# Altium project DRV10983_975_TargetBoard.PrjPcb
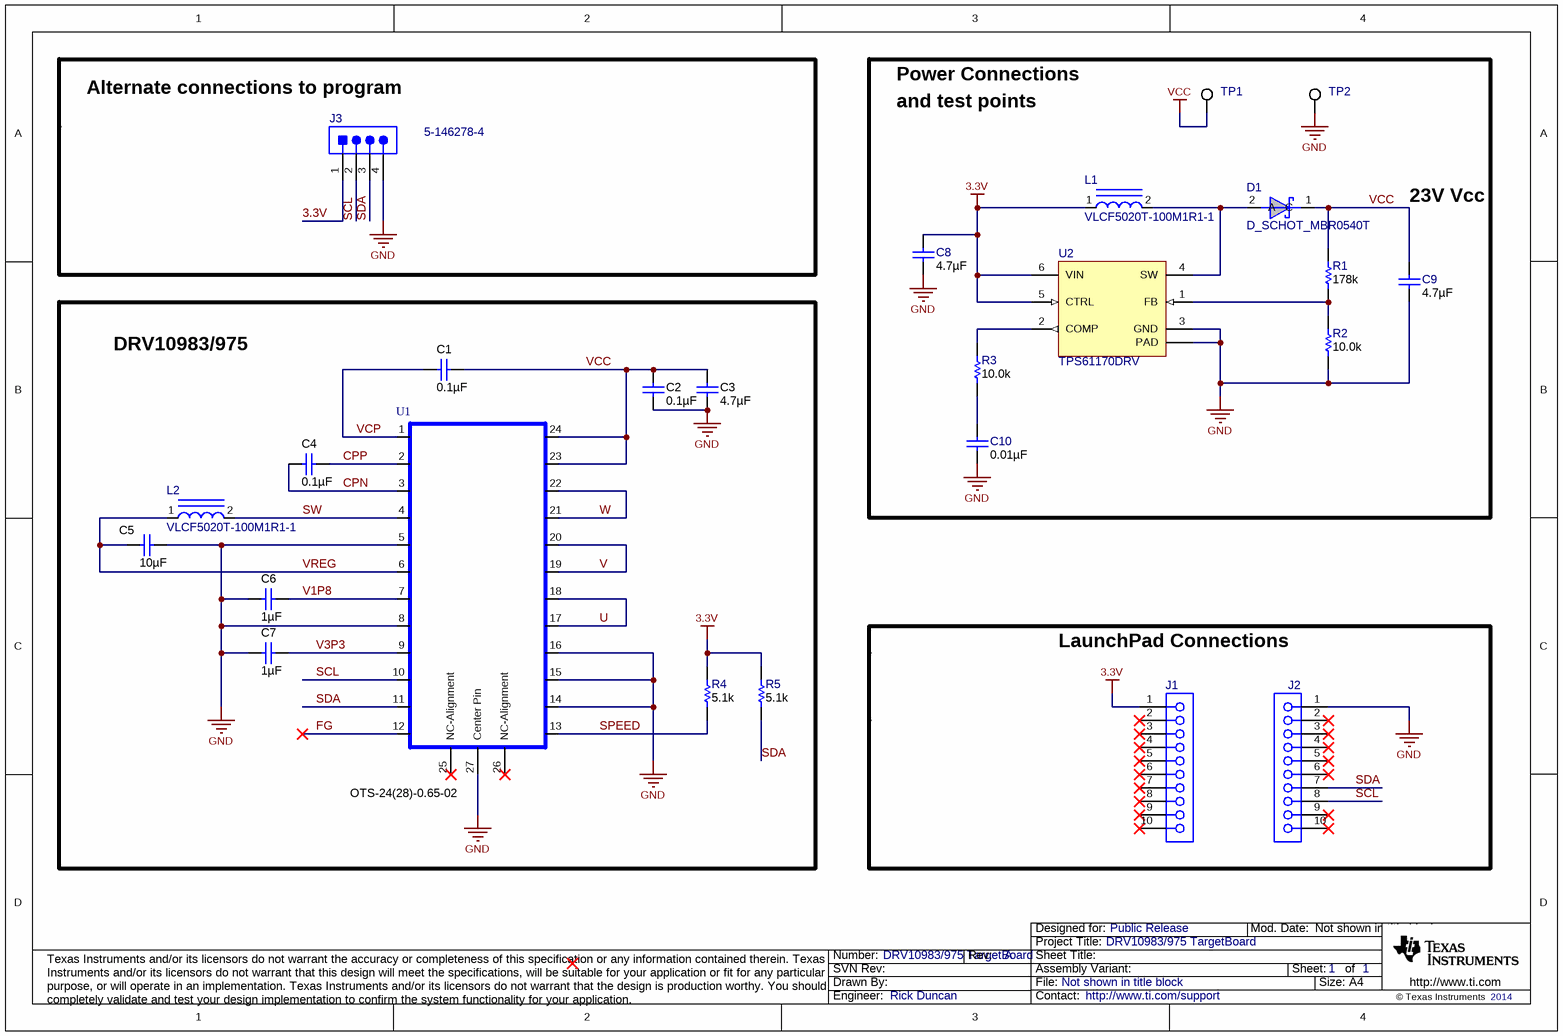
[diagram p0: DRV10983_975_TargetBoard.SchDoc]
TechSupport: http://www.ti.com/support; SCH_Rev: A; PRJ_Title: DRV10983/975 TargetBoard; PRJ_Number: DRV10983/975 TargetBoard; PRJ_Engineer: Rick Duncan; PRJ_Customer: Public Release; PCB_Rev: A; PCB_Layout: Rick Duncan; CopyrightYear: 2014
2 sheets, 31 parts. Net scope: global (net labels, ports and power ports of the same name join across sheets).
Board file: DRV10983_975_TargetBoard.PcbDoc
Sheets:
  DRV10983_975_TargetBoard.SchDoc
  Hardware_ANSI-B.SchDoc

## Sheet DRV10983_975_TargetBoard.SchDoc
size A4; Date: Not shown in title block; ApprovedBy: Not shown in title block; CheckedBy: Not shown in title block; Author: Not shown in title block; CompanyName: Not shown in title block; Engineer: Not shown in title block; Organization: Not shown in title block; Address1: Not shown in title block; Address2: Not shown in title block; Address3: Not shown in title block; Address4: Not shown in title block; DocumentNumber: 1; Revision: Use project parameter SCH_Rev; SheetNumber: 1; SheetTotal: 1; PageSetup: Record=PageOptions|CenterHorizontal=True|CenterVertical=True|PrintScale=0.91|XCorrection=1.00|YCorrection=1.00|PrintKind=0|BorderSize=5000000|LeftOffset=0|BottomOffset=0|Orientation=2|PaperLength=1000|PaperWidth=1000|Scale=100|PaperSource=15|PrintQuality=600|MediaType=1|DitherType=10|PaperKind=Letter|PrintScaleMode=1

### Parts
C1  ValueDisplayed: 0.1µF  [0603L]  (hidden comment: C1608X7R1H104K)
C2  ValueDisplayed: 0.1µF  [0603L]  (hidden comment: C1608X7R1H104K)
C3  ValueDisplayed: 4.7µF  [1210L]  (hidden comment: GRM32ER71H475KA88L)
C4  ValueDisplayed: 0.1µF  [0603L]  (hidden comment: C1608X7R1H104K)
C5  ValueDisplayed: 10µF  [1206_190]  (hidden comment: CGA5L3X5R1H106K160AB)
C6  ValueDisplayed: 1µF  [0603L]  (hidden comment: GRM188R61H105KAALD)
C7  ValueDisplayed: 1µF  [0603L]  (hidden comment: GRM188R61H105KAALD)
C8  ValueDisplayed: 4.7µF  [0603L]  (hidden comment: 0603ZD475KAT2A)
C9  ValueDisplayed: 4.7µF  [0805_HV]  (hidden comment: C2012X5R1H475K125AB)
C10  ValueDisplayed: 0.01µF  [0603L]  (hidden comment: C1608X7R1H103K)
D1  D_SCHOT_MBR0540T  [SOD-123]
J1  CRD-081413-B-T  [CONN_SSW-110-23-F-S]  (value not drawn)
J2  CRD-081413-B-T  [CONN_SSW-110-23-F-S]  (value not drawn)
J3  5-146278-4  [TE_5-146278-4]
L1  VLCF5020T-100M1R1-1  [IND_VLCF5020T]
L2  VLCF5020T-100M1R1-1  [IND_VLCF5020T]
R1  value 178k  [0603L]  (hidden comment: RC0603FR-07178KL)
R2  value 10.0k  [0603L]  (hidden comment: CRCW060310K0FKEA)
R3  value 10.0k  [0603L]  (hidden comment: CRCW060310K0FKEA)
R4  value 5.1k  [0603L]  (hidden comment: CRCW06035K10JNEA)
R5  value 5.1k  [0603L]  (hidden comment: CRCW06035K10JNEA)
TP1  5016  [Testpoint_Keystone_Compact]  (value not drawn)
TP2  5016  [Testpoint_Keystone_Compact]  (value not drawn)
U1  OTS-24(28)-0.65-02  [RECEPTACLE_OTS_24(28)-0.65-01_WCENTERPIN]
U2  TPS61170DRV  [DRV0006A]

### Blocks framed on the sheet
DRV10983/975: C1-C7 L2 R4 R5 U1

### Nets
3.3V: C8.1 J1.1 J3.1 L1.1 R4.2 R5.2 U2.5(CTRL) U2.6(VIN)
GND: C2.2 C3.1 C5.1 C6.1 C7.1 C8.2 C9.2 C10.2 J2.1 J3.4 R2.1 TP2.1 U1.5 U1.8 U1.14 U1.15 U1.16 U1.27(Center_Pin) U2.3(GND) U2.7(PAD)
VCC: C1.1 C2.1 C3.2 C9.1 D1.1(C) R1.2 TP1.1 U1.23 U1.24
CPN: C4.2 U1.3
CPP: C4.1 U1.2
FG: U1.12
SCL: J2.8 J3.2 U1.10
SDA: J2.7 J3.3 R5.1 U1.11
SPEED: R4.1 U1.13
SW: L2.2 U1.4
U: U1.17 U1.18
V: U1.19 U1.20
V1P8: C6.2 U1.7
V3P3: C7.2 U1.9
VCP: C1.2 U1.1
VREG: C5.2 L2.1 U1.6
W: U1.21 U1.22
NetC10_1: C10.1 R3.1
NetD1_2: D1.2(A) L1.2 U2.4(SW)
NetR1_1: R1.1 R2.2 U2.1(FB)
NetR3_2: R3.2 U2.2(COMP)

Not connected (* = marked no-connect by the designer): J1 2* 3* 4* 5* 6* 7* 8* 9* 10*; J2 2* 3* 4* 5* 6* 9* 10*; U1 25(NC-Alignment)* 26(NC-Alignment)*

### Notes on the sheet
- Alternate connections to program
- Power Connections
- and test points
- 23V Vcc
- LaunchPad Connections

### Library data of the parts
C1 C2 C4 = C1608X7R1H104K: CAP, CERM, 0.1uF, 50V, +/-10%, X7R, 0603; Manufacturer: TDK; Polarized: N; CompType: Capacitor; U/M: EA; Cap_F: 0.0000001; Tolerance_%: 10; ESR_Ohm: 0.017; Value1: 0.017 ohm; VDC_V: 50; TaMin_C: -55; TaMax_C: 125; Cap_Case: 0603
C3 = GRM32ER71H475KA88L: CAP, CERM, 4.7uF, 50V, +/-10%, X7R, 1210; Manufacturer: MuRata; Polarized: N; CompType: Capacitor; U/M: EA; Cap_F: 0.0000047; Tolerance_%: 10; ESR_Ohm: 0.002; Value1: 0.002 ohm; VDC_V: 50; TaMin_C: -55; TaMax_C: 125; Cap_Case: 1210
C5 = CGA5L3X5R1H106K160AB: CAP, CERM, 10uF, 50V, +/-10%, X5R, 1206_190; Manufacturer: TDK; Polarized: N; CompType: Capacitor; U/M: EA; Cap_F: 0.00001; Tolerance_%: 10; Value1: Unknown; VDC_V: 50; TaMin_C: -55; TaMax_C: 85
C6 C7 = GRM188R61H105KAALD: CAP, CERM, 1uF, 50V, +/-10%, X5R, 0603; Manufacturer: MuRata; Polarized: N; CompType: Capacitor; U/M: EA; Cap_F: 0.000001; Tolerance_%: 10; Value1: Unknown; VDC_V: 50; TaMin_C: -55; TaMax_C: 85; Cap_Case: 0603
C8 = 0603ZD475KAT2A: CAP, CERM, 4.7uF, 10V, +/-10%, X5R, 0603; Manufacturer: AVX; Polarized: N; CompType: Capacitor; U/M: EA; Cap_F: 0.0000047; Tolerance_%: 10; Value1: Unknown; TaMin_C: -55; TaMax_C: 85; Cap_Case: 0603
C9 = C2012X5R1H475K125AB: CAP, CERM, 4.7uF, 50V, +/-10%, X5R, 0805; Manufacturer: TDK; Polarized: N; CompType: Capacitor; U/M: EA; Cap_F: 0.0000047; Tolerance_%: 10; Value1: Unknown; VDC_V: 50; TaMin_C: -55; TaMax_C: 85; Cap_Case: 0805
C10 = C1608X7R1H103K: CAP, CERM, 0.01uF, 50V, +/-10%, X7R, 0603; Manufacturer: TDK; Polarized: N; CompType: Capacitor; U/M: EA; Cap_F: 0.00000001; Tolerance_%: 10; ESR_Ohm: 0.0539; Value1: 0.0539 ohm; VDC_V: 50; TaMin_C: -55; TaMax_C: 125; Cap_Case: 0603
D1 = D_SCHOT_MBR0540T: Diode, Schottky, 0.5A, 40V; Manufacturer: OnSemi; Area: 21500
J1 J2 = SSW-110-23-F-S: Connector, Receptacle, 100mil, 10x1, TH; Manufacturer: Major League Electronics; SymbolCreator: a0411947; U/M: EA
J3 = 5-146278-4: Header, 100mil, 4x1, Tin, TH; Manufacturer: TE Connectivity; SymbolCreator: a0412235; U/M: EA
L1 L2 = IND_VLCF5020T-SERIES: Inductor, SMT, yyA, zzmilliohm; Manufacturer: TDK; Area: 62100; Value: 10uH
R1 = RC0603FR-07178KL: RES, 178k ohm, 1%, 0.1W, 0603; Manufacturer: Yageo America; CompType: Resistor; Res_ohm: 178000; Tolerance_%: 1; Power_W: 0.1; VDC_V: 150; TempCo: 200 ppm/C; EIA_Code: E96; U/M: EA
R2 R3 = CRCW060310K0FKEA: RES, 10.0k ohm, 1%, 0.1W, 0603; Manufacturer: Vishay-Dale; CompType: Resistor; Res_ohm: 10000; Value_Code: 10k0; Tolerance_%: 1; Power_W: 0.1; VDC_V: 75; TempCo: 100 ppm/C; EIA_Code: E96; U/M: EA
R4 R5 = CRCW06035K10JNEA: RES, 5.1k ohm, 5%, 0.1W, 0603; Manufacturer: Vishay-Dale; CompType: Resistor; Res_ohm: 5100; Value_Code: 5k10; Tolerance_%: 5; Power_W: 0.1; VDC_V: 75; TempCo: 200 ppm/C; EIA_Code: E24; U/M: EA
TP1 TP2 = 5016: Test Point, Compact, SMT; Manufacturer: Keystone; CompType: Test Point Loop; U/M: EA
U1 = Receptacle_OTS-24(28)-065-01: Socket, 24 pin HTTOP no center pin; Manufacturer: Enplas; SymbolVersion: use current date i.e. 2008-05-20; SymbolCreator: Use a-id; CompType: Used in some BOM reports.  Useful for finding later.; U/M: EA, IN, or GM
U2 = TPS61170DRV: 1.2A High Voltage Boost Converter in 2x2mm QFN Package, DRV0006A; Alternate Manufacturer: None; Manufacturer: Texas Instruments; SymbolCreator: a0411947; CompType: IC; U/M: EA

## Sheet Hardware_ANSI-B.SchDoc
size 431 x 279 mm; Date: Not shown in title block; ApprovedBy: Not shown in title block; CheckedBy: Not shown in title block; Author: Not shown in title block; CompanyName: Not shown in title block; Engineer: Not shown in title block; Organization: Not shown in title block; Address1: Not shown in title block; Address2: Not shown in title block; Address3: Not shown in title block; Address4: Not shown in title block; DocumentNumber: 1; Revision: Use project parameter SCH_Rev; SheetNumber: 1; SheetTotal: 1; PageSetup: Record=PageOptions|CenterHorizontal=True|CenterVertical=True|PrintScale=1.00|XCorrection=1.00|YCorrection=1.00|PrintKind=0|BorderSize=5000000|LeftOffset=0|BottomOffset=0|Orientation=2|PaperLength=1000|PaperWidth=1000|Scale=100|PaperSource=15|PrintQuality=600|MediaType=1|DitherType=10|PaperKind=Letter|PrintScaleMode=1
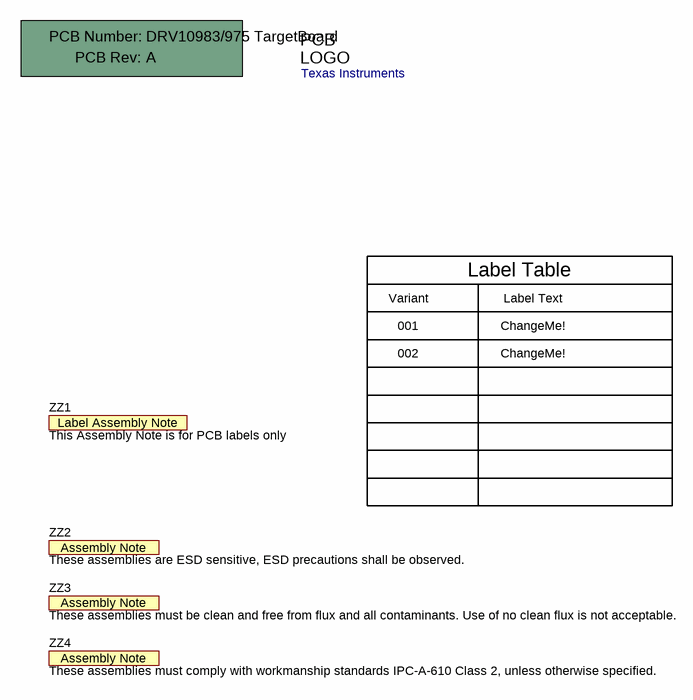
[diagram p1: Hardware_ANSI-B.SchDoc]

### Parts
!PCB  Printed Circuit Board  (value not drawn)  (mechanical)
Logo1  Texas Instruments  [TI_Stacked_Overlay_Small]  (no BOM)
ZZ1  This Assembly Note is for PCB labels only  [AssemblyNoteLabel]  (no BOM)
ZZ2  These assemblies are ESD sensitive, ESD precautions shall be observed.  [AssemblyNote]  (no BOM)
ZZ3  These assemblies must be clean and free from flux and all contaminants. Use of no clean flux is not acceptable.  [AssemblyNote]  (no BOM)
ZZ4  These assemblies must comply with workmanship standards IPC-A-610 Class 2, unless otherwise specified.  [AssemblyNote]  (no BOM)

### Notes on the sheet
- Variant
- Label Table
- Label Text
- 001
- 002
- ChangeMe!

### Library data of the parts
!PCB = PCB: Manufacturer: Any; PartNumber: DRV10983/975 TargetBoard; SymbolCreator: a0412235
Logo1 = TI_Logo: Texas Instrument Corporate Signature; SymbolCreator: a0412235
ZZ1 = AssemblyNoteLabel: SymbolCreator: a0412235
ZZ2-ZZ4 = AssemblyNote: SymbolCreator: codlsc

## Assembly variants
001: not fitted FID1 FID2 FID3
